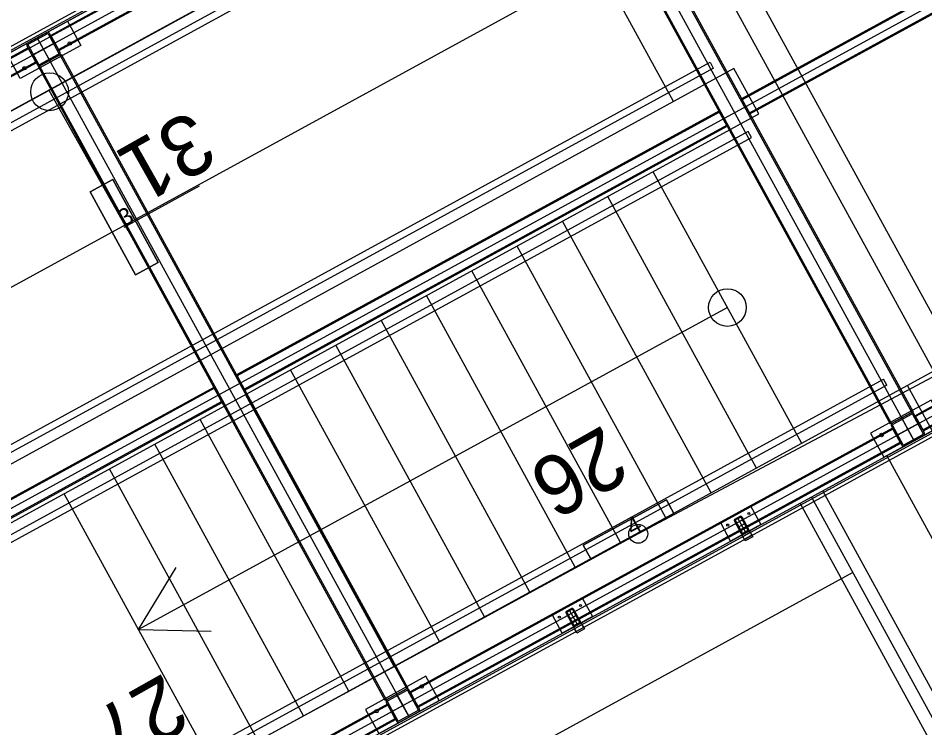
# Model space of a CAD drawing. Extents: x -783978 to -783565, y -1064821 to -1064596.
# Drawn here: x -783741.25 to -783735.98, y -1064671.69 to -1064667.56 of the extents above; entities that cross this region are included whole.
import ezdxf

# ---------------------------------------------------------------- set-up
doc = ezdxf.new("R2010")
doc.units = 0
for name, color, linetype in [('Default', 7, 'Continuous'), ('SO 01_20_01', 7, 'Continuous'), ('SO 01_50_01', 7, 'Continuous'), ('SO 01_74_01', 7, 'Continuous'), ('SO 01_86_04', 7, 'Continuous')]:
    doc.layers.add(name, color=color, linetype=linetype)

# ---------------------------------------------------------------- blocks, each defined once
blk = doc.blocks.new('POINT_DISPLAY')
at = {"layer": 'Default'}
blk.add_line((0, 0), (0, 0), dxfattribs=at)

msp = doc.modelspace()

# ---------------------------------------------------------------- linework, layer by layer
at = {"layer": 'SO 01_20_01'}
for p, q in [((-783735.2041, -1064664.4318), (-783786.7885, -1064692.6541)), ((-783786.6445, -1064692.9173), (-783735.3233, -1064664.839)), ((-783735.7981, -1064669.5443), (-783737.67, -1064666.1229)), ((-783737.4421, -1064668.05), (-783738.45, -1064666.2077)), ((-783735.9297, -1064669.6163), (-783737.8016, -1064666.1949)), ((-783738.0171, -1064666.3812), (-783786.4402, -1064692.874)), ((-783786.421, -1064692.9091), (-783737.9979, -1064666.4163)), ((-783737.4421, -1064668.05), (-783738.3061, -1064666.4709)), ((-783737.8741, -1064667.2605), (-783785.3352, -1064693.2269)), ((-783785.6531, -1064694.3127), (-783737.23, -1064667.82)), ((-783737.23, -1064667.82), (-783737.2109, -1064667.8547)), ((-783737.0912, -1064667.858), (-783785.7805, -1064694.4964)), ((-783737.2108, -1064667.855), (-783785.6339, -1064694.3478)), ((-783736.9472, -1064668.1212), (-783737.0912, -1064667.858)), ((-783785.6366, -1064694.7596), (-783736.9472, -1064668.1212)), ((-783737.0092, -1064668.2235), (-783746.0685, -1064673.1799)), ((-783736.99, -1064668.2586), (-783737.0092, -1064668.2235)), ((-783746.0493, -1064673.215), (-783736.99, -1064668.2586)), ((-783733.4514, -1064668.2604), (-783745.2333, -1064674.7064)), ((-783745.0893, -1064674.9696), (-783733.0442, -1064668.3796)), ((-783736.6974, -1064670.0363), (-783737.5613, -1064668.4572)), ((-783736.6974, -1064670.0363), (-783737.5613, -1064668.4572)), ((-783736.9605, -1064670.1803), (-783737.8245, -1064668.6012)), ((-783737.2237, -1064670.3243), (-783738.0877, -1064668.7452)), ((-783737.4869, -1064670.4683), (-783738.3509, -1064668.8892)), ((-783737.7501, -1064670.6123), (-783738.614, -1064669.0332)), ((-783738.0133, -1064670.7563), (-783738.8772, -1064669.1771)), ((-783737.1293, -1064669.2467), (-783740.5507, -1064671.1186)), ((-783738.2765, -1064670.9002), (-783739.1404, -1064669.3211)), ((-783738.5397, -1064671.0442), (-783739.4036, -1064669.4651)), ((-783738.8028, -1064671.1882), (-783739.6668, -1064669.6091)), ((-783745.2813, -1064674.6187), (-783736.222, -1064669.6623)), ((-783736.2028, -1064669.6973), (-783736.222, -1064669.6623)), ((-783736.2028, -1064669.6973), (-783745.2621, -1064674.6538)), ((-783735.7041, -1064670.3934), (-783736.0833, -1064669.7003)), ((-783739.066, -1064671.3322), (-783739.93, -1064669.7531)), ((-783739.3292, -1064671.4762), (-783740.1932, -1064669.8971)), ((-783739.5924, -1064671.6202), (-783740.4563, -1064670.0411)), ((-783729.1709, -1064682.9597), (-783736.2025, -1064670.1075)), ((-783739.8556, -1064671.7642), (-783740.7195, -1064670.1851)), ((-783740.1188, -1064671.9082), (-783740.9827, -1064670.3291)), ((-783732.4653, -1064677.9799), (-783736.6411, -1064670.3475)), ((-783732.3925, -1064677.9567), (-783736.5753, -1064670.3115)), ((-783732.5241, -1064678.0287), (-783736.7069, -1064670.3835)), ((-783740.5507, -1064671.1186), (-783740.3312, -1064670.7578)), ((-783736.4011, -1064670.7861), (-783745.288, -1064675.6482)), ((-783740.5507, -1064671.1186), (-783740.1284, -1064671.1283))]:
    msp.add_line(p, q, dxfattribs=at)
msp.add_circle((-783737.1293, -1064669.2467), 0.1095, dxfattribs=at)
at = {"layer": 'SO 01_50_01'}
for p, q in [((-783786.7885, -1064692.6541), (-783725.4827, -1064659.1131)), ((-783742.9243, -1064668.6556), (-783738.5378, -1064666.2557)), ((-783742.9242, -1064668.6557), (-783738.5378, -1064666.2558)), ((-783742.9242, -1064668.6557), (-783738.5378, -1064666.2558))]:
    msp.add_line(p, q, dxfattribs=at)
at = {"layer": 'SO 01_74_01'}
for p, q in [((-783735.2185, -1064664.4055), (-783786.6099, -1064692.5222)), ((-783786.6003, -1064692.5398), (-783735.2089, -1064664.423)), ((-783738.2582, -1064666.1313), (-783741.061, -1064667.6647)), ((-783738.2552, -1064666.1368), (-783741.058, -1064667.6702)), ((-783738.0736, -1064666.1728), (-783736.0578, -1064669.8574)), ((-783738.0666, -1064666.1689), (-783736.0507, -1064669.8535)), ((-783741.016, -1064667.7469), (-783738.2132, -1064666.2135)), ((-783741.013, -1064667.7524), (-783738.2102, -1064666.219)), ((-783736.1823, -1064669.9255), (-783738.1982, -1064666.2409)), ((-783736.1753, -1064669.9217), (-783738.1912, -1064666.2371)), ((-783734.2438, -1064666.4996), (-783737.0465, -1064668.0331)), ((-783734.2407, -1064666.5052), (-783737.0435, -1064668.0386)), ((-783737.0016, -1064668.1153), (-783734.1988, -1064666.5818)), ((-783736.9985, -1064668.1208), (-783734.1958, -1064666.5874)), ((-783741.061, -1064667.6647), (-783741.013, -1064667.7524)), ((-783741.058, -1064667.6702), (-783741.016, -1064667.7469)), ((-783741.1927, -1064667.7368), (-783743.9955, -1064669.2702)), ((-783741.1897, -1064667.7423), (-783743.9925, -1064669.2757)), ((-783741.1447, -1064667.8245), (-783741.1927, -1064667.7368)), ((-783741.1477, -1064667.819), (-783741.1897, -1064667.7423)), ((-783743.9505, -1064669.3524), (-783741.1477, -1064667.819)), ((-783743.9475, -1064669.3579), (-783741.1447, -1064667.8245)), ((-783741.1327, -1064667.8464), (-783741.0011, -1064667.7744)), ((-783741.1257, -1064667.8426), (-783741.0082, -1064667.7783)), ((-783741.0082, -1064667.7783), (-783738.9923, -1064671.4629)), ((-783741.0011, -1064667.7744), (-783738.9853, -1064671.459)), ((-783739.1168, -1064671.531), (-783741.1327, -1064667.8464)), ((-783739.1098, -1064671.5272), (-783741.1257, -1064667.8426)), ((-783737.0465, -1064668.0331), (-783736.9985, -1064668.1208)), ((-783737.0435, -1064668.0386), (-783737.0016, -1064668.1153)), ((-783737.1783, -1064668.1051), (-783739.9811, -1064669.6386)), ((-783737.1752, -1064668.1107), (-783739.978, -1064669.6441)), ((-783737.1303, -1064668.1929), (-783737.1783, -1064668.1051)), ((-783737.1333, -1064668.1873), (-783737.1752, -1064668.1107)), ((-783739.9361, -1064669.7208), (-783737.1333, -1064668.1873)), ((-783739.9331, -1064669.7263), (-783737.1303, -1064668.1929)), ((-783733.2358, -1064668.3419), (-783736.0386, -1064669.8754)), ((-783733.2328, -1064668.3475), (-783736.0356, -1064669.8809)), ((-783744.8433, -1064674.8464), (-783733.0394, -1064668.3884)), ((-783733.0298, -1064668.4059), (-783744.8337, -1064674.8639)), ((-783735.9936, -1064669.9576), (-783733.1908, -1064668.4241)), ((-783735.9906, -1064669.9631), (-783733.1878, -1064668.4297)), ((-783739.9811, -1064669.6386), (-783739.9331, -1064669.7263)), ((-783739.978, -1064669.6441), (-783739.9361, -1064669.7208)), ((-783740.1128, -1064669.7106), (-783742.9156, -1064671.2441)), ((-783740.1098, -1064669.7162), (-783742.9126, -1064671.2496)), ((-783740.0648, -1064669.7984), (-783740.1128, -1064669.7106)), ((-783740.0678, -1064669.7928), (-783740.1098, -1064669.7162)), ((-783742.8706, -1064671.3263), (-783740.0678, -1064669.7928)), ((-783742.8676, -1064671.3318), (-783740.0648, -1064669.7984)), ((-783736.0507, -1064669.8535), (-783736.1823, -1064669.9255)), ((-783736.0578, -1064669.8574), (-783736.1753, -1064669.9217)), ((-783736.0386, -1064669.8754), (-783735.9906, -1064669.9631)), ((-783736.0356, -1064669.8809), (-783735.9936, -1064669.9576)), ((-783736.1703, -1064669.9474), (-783738.9731, -1064671.4809)), ((-783736.1673, -1064669.953), (-783738.9701, -1064671.4864)), ((-783736.1223, -1064670.0352), (-783736.1703, -1064669.9474)), ((-783736.1254, -1064670.0296), (-783736.1673, -1064669.953)), ((-783738.9281, -1064671.5631), (-783736.1254, -1064670.0296)), ((-783738.9251, -1064671.5686), (-783736.1223, -1064670.0352)), ((-783737.0446, -1064670.5683), (-783737.0008, -1064670.5443)), ((-783737.0398, -1064670.577), (-783736.996, -1064670.553)), ((-783737.0008, -1064670.5443), (-783736.9816, -1064670.5794)), ((-783736.996, -1064670.553), (-783736.9864, -1064670.5706)), ((-783737.0254, -1064670.6034), (-783737.0446, -1064670.5683)), ((-783737.0302, -1064670.5946), (-783737.0398, -1064670.577)), ((-783736.9864, -1064670.5706), (-783737.0302, -1064670.5946)), ((-783736.9816, -1064670.5794), (-783737.0254, -1064670.6034)), ((-783738.0228, -1064671.1034), (-783737.979, -1064671.0794)), ((-783738.018, -1064671.1122), (-783737.9742, -1064671.0882)), ((-783737.979, -1064671.0794), (-783737.9598, -1064671.1145)), ((-783737.9742, -1064671.0882), (-783737.9646, -1064671.1058)), ((-783738.0036, -1064671.1385), (-783738.0228, -1064671.1034)), ((-783738.0084, -1064671.1298), (-783738.018, -1064671.1122)), ((-783737.9646, -1064671.1058), (-783738.0084, -1064671.1298)), ((-783737.9598, -1064671.1145), (-783738.0036, -1064671.1385)), ((-783738.9853, -1064671.459), (-783739.1168, -1064671.531)), ((-783738.9923, -1064671.4629), (-783739.1098, -1064671.5272)), ((-783738.9731, -1064671.4809), (-783738.9251, -1064671.5686)), ((-783738.9701, -1064671.4864), (-783738.9281, -1064671.5631)), ((-783739.1048, -1064671.5529), (-783741.9076, -1064673.0864)), ((-783739.1018, -1064671.5585), (-783741.9046, -1064673.0919)), ((-783739.0569, -1064671.6407), (-783739.1048, -1064671.5529)), ((-783739.0599, -1064671.6351), (-783739.1018, -1064671.5585)), ((-783741.8627, -1064673.1686), (-783739.0599, -1064671.6351)), ((-783741.8596, -1064673.1741), (-783739.0569, -1064671.6407))]:
    msp.add_line(p, q, dxfattribs=at)
for points in [[(-783735.1681, -1064664.4976), (-783787.4762, -1064693.1159)], [(-783738.2044, -1064666.0733), (-783736.0445, -1064670.0211)], [(-783734.0882, -1064666.4715), (-783786.3963, -1064695.0898)], [(-783741.0837, -1064667.6486), (-783741.1942, -1064667.7091)], [(-783741.0798, -1064667.6556), (-783741.1904, -1064667.7161)], [(-783741.0139, -1064667.7677), (-783741.0744, -1064667.6572)], [(-783741.0069, -1064667.7639), (-783741.0674, -1064667.6534)], [(-783741.0371, -1064667.7086), (-783741.1687, -1064667.7806)], [(-783741.1389, -1064667.6788), (-783738.9791, -1064671.6266)], [(-783741.0669, -1064667.8104), (-783741.1389, -1064667.6788)], [(-783741.199, -1064667.7253), (-783741.1385, -1064667.8359)], [(-783741.1919, -1064667.7215), (-783741.1315, -1064667.832)], [(-783741.126, -1064667.8336), (-783741.0155, -1064667.7732)], [(-783741.1222, -1064667.8407), (-783741.0117, -1064667.7802)], [(-783733.0802, -1064668.3138), (-783745.8491, -1064675.2998)], [(-783736.0613, -1064669.8593), (-783736.1718, -1064669.9197)], [(-783736.0574, -1064669.8663), (-783736.168, -1064669.9268)], [(-783735.9915, -1064669.9784), (-783736.052, -1064669.8679)], [(-783735.9845, -1064669.9746), (-783736.045, -1064669.864)], [(-783736.1696, -1064669.9322), (-783736.1091, -1064670.0427)], [(-783736.0147, -1064669.9193), (-783736.1463, -1064669.9913)], [(-783736.0445, -1064670.0211), (-783736.1165, -1064669.8895)], [(-783736.1766, -1064669.936), (-783736.1161, -1064670.0466)], [(-783736.1036, -1064670.0443), (-783735.9931, -1064669.9838)], [(-783736.0998, -1064670.0513), (-783735.9893, -1064669.9909)], [(-783737.0881, -1064670.4888), (-783737.0492, -1064670.56)], [(-783737.0571, -1064670.4611), (-783737.0844, -1064670.476)], [(-783737.0826, -1064670.4858), (-783737.0437, -1064670.557)], [(-783737.054, -1064670.4666), (-783737.0813, -1064670.4815)], [(-783737.0707, -1064670.4685), (-783737.0227, -1064670.5563)], [(-783737.0248, -1064670.5004), (-783737.0686, -1064670.5244)], [(-783737.0108, -1064670.539), (-783737.0498, -1064670.4679)], [(-783737.0053, -1064670.536), (-783737.0442, -1064670.4648)], [(-783737.0394, -1064670.5582), (-783737.0121, -1064670.5433)], [(-783737.0364, -1064670.5637), (-783737.0091, -1064670.5488)], [(-783738.0663, -1064671.024), (-783738.0274, -1064671.0951)], [(-783738.0352, -1064670.9962), (-783738.0625, -1064671.0112)], [(-783738.0608, -1064671.021), (-783738.0218, -1064671.0921)], [(-783738.0322, -1064671.0018), (-783738.0595, -1064671.0167)], [(-783738.0489, -1064671.0037), (-783738.0009, -1064671.0914)], [(-783738.003, -1064671.0356), (-783738.0468, -1064671.0596)], [(-783737.989, -1064671.0742), (-783738.0279, -1064671.003)], [(-783737.9835, -1064671.0711), (-783738.0224, -1064671)], [(-783738.0176, -1064671.0934), (-783737.9903, -1064671.0784)], [(-783738.0145, -1064671.0989), (-783737.9872, -1064671.084)], [(-783738.9958, -1064671.4648), (-783739.1063, -1064671.5252)], [(-783738.9919, -1064671.4718), (-783739.1025, -1064671.5323)], [(-783738.9791, -1064671.6266), (-783739.0511, -1064671.495)], [(-783738.926, -1064671.5839), (-783738.9865, -1064671.4734)], [(-783738.919, -1064671.5801), (-783738.9795, -1064671.4695)], [(-783739.1111, -1064671.5415), (-783739.0506, -1064671.6521)], [(-783739.1041, -1064671.5377), (-783739.0436, -1064671.6482)], [(-783738.9493, -1064671.5248), (-783739.0809, -1064671.5968)], [(-783739.0382, -1064671.6498), (-783738.9276, -1064671.5893)], [(-783739.0343, -1064671.6568), (-783738.9238, -1064671.5964)]]:
    msp.add_lwpolyline(points, dxfattribs=at)
for points in [[(-783740.8867, -1064667.7232), (-783741.2376, -1064667.9152), (-783741.3144, -1064667.7748), (-783740.9635, -1064667.5828)], [(-783735.9459, -1064669.7847), (-783736.2968, -1064669.9767), (-783736.22, -1064670.1171), (-783735.8691, -1064669.9251)], [(-783736.935, -1064670.5083), (-783737.1104, -1064670.6043), (-783737.168, -1064670.499), (-783736.9926, -1064670.403)], [(-783737.9132, -1064671.0434), (-783738.0886, -1064671.1394), (-783738.1462, -1064671.0342), (-783737.9708, -1064670.9382)], [(-783738.8804, -1064671.3902), (-783739.2313, -1064671.5822), (-783739.1545, -1064671.7226), (-783738.8036, -1064671.5306)]]:
    msp.add_lwpolyline(points, close=True, dxfattribs=at)
for centre, radius in [((-783740.9497, -1064667.7121), 0.01), ((-783741.2129, -1064667.8561), 0.01), ((-783736.2337, -1064669.9878), 0.01), ((-783737.0045, -1064670.4437), 0.006), ((-783737.1273, -1064670.5109), 0.006), ((-783737.9827, -1064670.9789), 0.006), ((-783738.1055, -1064671.0461), 0.006), ((-783738.9051, -1064671.4493), 0.01), ((-783739.1682, -1064671.5933), 0.01)]:
    msp.add_circle(centre, radius, dxfattribs=at)
for centre, radius, start, end in [((-783741.0779, -1064667.6591), 0.012, 28.6835, 118.6835), ((-783741.0779, -1064667.6591), 0.004, 28.6835, 118.6835), ((-783741.1884, -1064667.7196), 0.012, 118.6835, 208.6835), ((-783741.1884, -1064667.7196), 0.004, 118.6835, 208.6835), ((-783741.0174, -1064667.7697), 0.004, 298.6835, 28.6835), ((-783741.0174, -1064667.7697), 0.012, 298.6835, 28.6835), ((-783741.128, -1064667.8301), 0.012, 208.6835, 298.6835), ((-783741.128, -1064667.8301), 0.004, 208.6835, 298.6835), ((-783736.0555, -1064669.8698), 0.012, 28.6835, 118.6835), ((-783736.0555, -1064669.8698), 0.004, 28.6835, 118.6835), ((-783736.166, -1064669.9303), 0.012, 118.6835, 208.6835), ((-783736.166, -1064669.9303), 0.004, 118.6835, 208.6835), ((-783735.995, -1064669.9803), 0.004, 298.6835, 28.6835), ((-783735.995, -1064669.9803), 0.012, 298.6835, 28.6835), ((-783736.1056, -1064670.0408), 0.012, 208.6835, 298.6835), ((-783736.1056, -1064670.0408), 0.004, 208.6835, 298.6835), ((-783737.0798, -1064670.4843), 0.00945, 118.6835, 208.6835), ((-783737.0798, -1064670.4843), 0.00315, 118.6835, 208.6835), ((-783737.0525, -1064670.4694), 0.00945, 28.6835, 118.6835), ((-783737.0525, -1064670.4694), 0.00315, 28.6835, 118.6835), ((-783737.0409, -1064670.5554), 0.00945, 208.6835, 298.6835), ((-783737.0409, -1064670.5554), 0.00315, 208.6835, 298.6835), ((-783737.0136, -1064670.5405), 0.00315, 298.6835, 28.6835), ((-783737.0136, -1064670.5405), 0.00945, 298.6835, 28.6835), ((-783738.058, -1064671.0195), 0.00945, 118.6835, 208.6835), ((-783738.058, -1064671.0195), 0.00315, 118.6835, 208.6835), ((-783738.0307, -1064671.0045), 0.00945, 28.6835, 118.6835), ((-783738.0307, -1064671.0045), 0.00315, 28.6835, 118.6835), ((-783737.9918, -1064671.0757), 0.00315, 298.6835, 28.6835), ((-783737.9918, -1064671.0757), 0.00945, 298.6835, 28.6835), ((-783738.0191, -1064671.0906), 0.00945, 208.6835, 298.6835), ((-783738.0191, -1064671.0906), 0.00315, 208.6835, 298.6835), ((-783738.99, -1064671.4753), 0.012, 28.6835, 118.6835), ((-783738.99, -1064671.4753), 0.004, 28.6835, 118.6835), ((-783739.1006, -1064671.5358), 0.012, 118.6835, 208.6835), ((-783739.1006, -1064671.5358), 0.004, 118.6835, 208.6835), ((-783738.9295, -1064671.5858), 0.004, 298.6835, 28.6835), ((-783738.9295, -1064671.5858), 0.012, 298.6835, 28.6835), ((-783739.0401, -1064671.6463), 0.012, 208.6835, 298.6835), ((-783739.0401, -1064671.6463), 0.004, 208.6835, 298.6835)]:
    msp.add_arc(centre, radius, start, end, dxfattribs=at)
at = {"layer": 'SO 01_86_04'}
for p, q in [((-783741.0723, -1064667.9843), (-783740.6122, -1064668.799)), ((-783740.7006, -1064668.502), (-783740.8322, -1064668.574)), ((-783740.7006, -1064668.502), (-783740.8322, -1064668.574)), ((-783740.8322, -1064668.574), (-783740.7006, -1064668.502)), ((-783740.8322, -1064668.574), (-783740.7006, -1064668.502)), ((-783740.4366, -1064668.9845), (-783740.7006, -1064668.502)), ((-783740.4366, -1064668.9845), (-783740.7006, -1064668.502)), ((-783740.7006, -1064668.502), (-783740.4366, -1064668.9845)), ((-783740.7006, -1064668.502), (-783740.4366, -1064668.9845)), ((-783740.6344, -1064668.7793), (-783740.1957, -1064668.5393)), ((-783740.8322, -1064668.574), (-783740.5682, -1064669.0565)), ((-783740.8322, -1064668.574), (-783740.5682, -1064669.0565)), ((-783740.5682, -1064669.0565), (-783740.8322, -1064668.574)), ((-783740.5682, -1064669.0565), (-783740.8322, -1064668.574)), ((-783740.5682, -1064669.0565), (-783740.4366, -1064668.9845)), ((-783740.5682, -1064669.0565), (-783740.4366, -1064668.9845)), ((-783740.4366, -1064668.9845), (-783740.5682, -1064669.0565)), ((-783740.4366, -1064668.9845), (-783740.5682, -1064669.0565)), ((-783737.4838, -1064670.364), (-783737.9663, -1064670.628)), ((-783737.9663, -1064670.628), (-783737.4838, -1064670.364)), ((-783737.9663, -1064670.628), (-783737.4838, -1064670.364)), ((-783737.4838, -1064670.364), (-783737.9663, -1064670.628)), ((-783737.4406, -1064670.4429), (-783737.4838, -1064670.364)), ((-783737.4838, -1064670.364), (-783737.4406, -1064670.4429)), ((-783737.4406, -1064670.4429), (-783737.4838, -1064670.364)), ((-783737.4838, -1064670.364), (-783737.4406, -1064670.4429)), ((-783737.9231, -1064670.7069), (-783737.4406, -1064670.4429)), ((-783737.4406, -1064670.4429), (-783737.9231, -1064670.7069)), ((-783737.9231, -1064670.7069), (-783737.4406, -1064670.4429)), ((-783737.4406, -1064670.4429), (-783737.9231, -1064670.7069)), ((-783737.9663, -1064670.628), (-783737.9231, -1064670.7069)), ((-783737.9231, -1064670.7069), (-783737.9663, -1064670.628)), ((-783737.9663, -1064670.628), (-783737.9231, -1064670.7069)), ((-783737.9231, -1064670.7069), (-783737.9663, -1064670.628))]:
    msp.add_line(p, q, dxfattribs=at)
for points in [[(-783735.4626, -1064664.5844), (-783749.7616, -1064672.4637), (-783749.643, -1064672.6735)], [(-783738.3222, -1064666.4797), (-783740.5325, -1064667.689), (-783743.1715, -1064669.1328), (-783745.7538, -1064670.5456), (-783748.4385, -1064672.0145), (-783751.0413, -1064673.4385), (-783753.6847, -1064674.8847), (-783756.3281, -1064676.3309), (-783758.9715, -1064677.7772), (-783761.6149, -1064679.2234), (-783764.2583, -1064680.6696), (-783766.9018, -1064682.1159), (-783769.4633, -1064683.5173), (-783772.109, -1064684.9648), (-783774.7882, -1064686.4306), (-783778.1382, -1064688.2722), (-783783.8139, -1064691.3971), (-783785.747, -1064692.4898)], [(-783733.4229, -1064668.3125), (-783737.6471, -1064670.5617), (-783739.9521, -1064671.817), (-783742.6942, -1064673.3169), (-783745.0268, -1064674.6345), (-783745.4136, -1064673.9496)]]:
    msp.add_lwpolyline(points, dxfattribs=at)
for centre, radius in [((-783741.0676, -1064667.9928), 0.1097), ((-783737.6471, -1064670.5617), 0.0549)]:
    msp.add_circle(centre, radius, dxfattribs=at)

# ---------------------------------------------------------------- block references
at = {"layer": 'SO 01_86_04', "xscale": 0.010000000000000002, "yscale": 0.009999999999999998, "rotation": 28.683491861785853}
for p in [(-783740.7006, -1064668.502), (-783740.7006, -1064668.502), (-783740.8322, -1064668.574), (-783740.8322, -1064668.574), (-783740.4366, -1064668.9845), (-783740.4366, -1064668.9845), (-783740.5682, -1064669.0565), (-783740.5682, -1064669.0565), (-783737.4838, -1064670.364), (-783737.4838, -1064670.364), (-783737.4406, -1064670.4429), (-783737.4406, -1064670.4429), (-783737.725, -1064670.496), (-783737.9663, -1064670.628), (-783737.9663, -1064670.628), (-783737.9231, -1064670.7069), (-783737.9231, -1064670.7069)]:
    msp.add_blockref('POINT_DISPLAY', p, dxfattribs=at)

# ---------------------------------------------------------------- texts
at = {"layer": 'SO 01_86_04'}
for s, height, rotation, p in [('31', 0.351, 209.46, (-783740.2433, -1064668.0915)), ('3', 0.1, 28.6835, (-783740.6344, -1064668.7793)), ('26', 0.351, 209.46, (-783737.8481, -1064669.9251)), ('4', 0.1, 28.6835, (-783737.6818, -1064670.5749)), ('27', 0.351, 209.46, (-783740.4012, -1064671.3672))]:
    msp.add_text(s, height=height, rotation=rotation, dxfattribs=at).set_placement(p)

doc.saveas('drawing.dxf')
